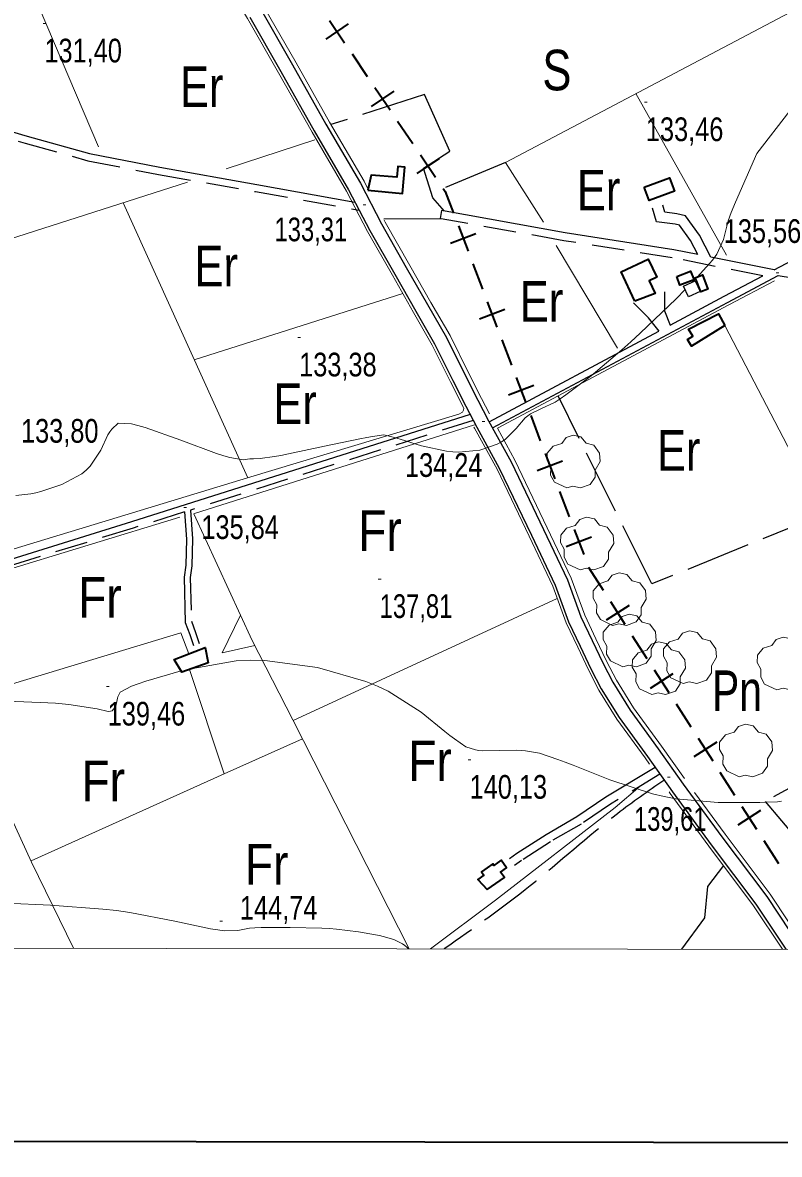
# Model space of a CAD drawing. Extents: x 487425 to 492029, y 4383576 to 4386788.
# Drawn here: x 488050.9 to 488330.4, y 4384052.3 to 4384470.4 of the extents above; entities that cross this region are included whole.
import ezdxf
from ezdxf.enums import TextEntityAlignment as Align

# ---------------------------------------------------------------- set-up
doc = ezdxf.new("R2010")
doc.units = 0
doc.header["$LTSCALE"] = 4
doc.linetypes.add('LONG_DASHED', pattern=[7.5, 6, -1.5])
doc.linetypes.add('MEDIUM_DASHED', pattern=[4.5, 3, -1.5])
for name, color, linetype, lineweight in [('1', 7, 'Continuous', 13), ('21', 7, 'Continuous', 25), ('25', 7, 'LONG_DASHED', 25), ('29', 7, 'Continuous', 13), ('34', 7, 'Continuous', 35), ('36', 7, 'Continuous', 25), ('38', 7, 'Continuous', 25), ('47', 7, 'Continuous', 35), ('51', 7, 'Continuous', 13), ('7', 7, 'Continuous', 13), ('9', 7, 'Continuous', 13)]:
    doc.layers.add(name, color=color, linetype=linetype, lineweight=lineweight)
doc.layers.add('31', color=7, linetype='Continuous')

msp = doc.modelspace()

# ---------------------------------------------------------------- linework, layer by layer
at = {"layer": '1', "lineweight": 35}
msp.add_lwpolyline([(487611.46, 4386512.7), (491328.86, 4386507.3), (491325.3, 4384052.3), (487607.9, 4384057.7)], close=True, dxfattribs=at)
at = {"layer": '1'}
msp.add_lwpolyline([(487681.9, 4386441.2), (491258.2, 4386436), (491255.4, 4384123.8), (487678, 4384129)], close=True, dxfattribs=at)
at = {"layer": '21'}
msp.add_lwpolyline([(488295.04, 4384373.01), (488299.32, 4384375.02), (488301.17, 4384371.07), (488296.89, 4384369.06)], close=True, dxfattribs=at)
at = {"layer": '25'}
for p, q in [((488229.24, 4384418.77), (488201.91, 4384407.26)), ((488205.48, 4384397.97), (488184.27, 4384397.75))]:
    msp.add_line(p, q, dxfattribs=at)
for points in [[(488206.75, 4384400.79), (488202.39, 4384405.72), (488198.91, 4384416.64), (488208.66, 4384422.91), (488199.29, 4384443.8), (488164.78, 4384432.73)], [(488346.6, 4384288.7), (488283.29, 4384263.01), (488248.67, 4384332.48)], [(488500.54, 4384232.57), (488391.47, 4384171.16), (488380.26, 4384174.51), (488371.03, 4384181.22), (488361.77, 4384197.9), (488349.22, 4384195.94), (488325.13, 4384182.64), (488337.28, 4384168.32), (488347.47, 4384167.38), (488352.97, 4384162.67), (488357.34, 4384157.74), (488366.14, 4384147.21), (488370.51, 4384135.61), (488372.62, 4384127.99)], [(488309.75, 4384159.04), (488303.85, 4384151.3), (488302.81, 4384139.68), (488294.31, 4384128.1)]]:
    msp.add_lwpolyline(points, dxfattribs=at)
at = {"layer": '29'}
for points in [[(488251.86, 4384298.56), (488247.32, 4384300.68), (488245.91, 4384303.22), (488246.01, 4384306.2), (488244.64, 4384308.61), (488244.68, 4384311.36), (488246.84, 4384313.96), (488250.03, 4384314.96), (488251.68, 4384317.15), (488254.25, 4384317.98), (488257.11, 4384317.33), (488259.06, 4384315.06), (488261.87, 4384314.24), (488264, 4384311.39), (488264.24, 4384308.26), (488262.36, 4384305.11), (488262.36, 4384302.43), (488260.54, 4384299.82), (488256.92, 4384298.48), (488254.15, 4384299.11)], [(488256.84, 4384268.27), (488252.3, 4384270.39), (488250.89, 4384272.93), (488250.99, 4384275.91), (488249.62, 4384278.32), (488249.66, 4384281.07), (488251.82, 4384283.67), (488255.01, 4384284.67), (488256.66, 4384286.86), (488259.23, 4384287.69), (488262.09, 4384287.04), (488264.04, 4384284.77), (488266.85, 4384283.95), (488268.98, 4384281.1), (488269.22, 4384277.97), (488267.34, 4384274.82), (488267.34, 4384272.14), (488265.52, 4384269.53), (488261.9, 4384268.19), (488259.13, 4384268.82)], [(488268.84, 4384247.73), (488264.3, 4384249.85), (488262.89, 4384252.39), (488262.99, 4384255.37), (488261.62, 4384257.78), (488261.66, 4384260.53), (488263.82, 4384263.13), (488267.01, 4384264.13), (488268.66, 4384266.32), (488271.23, 4384267.15), (488274.09, 4384266.5), (488276.04, 4384264.23), (488278.85, 4384263.41), (488280.98, 4384260.56), (488281.22, 4384257.43), (488279.34, 4384254.28), (488279.34, 4384251.6), (488277.52, 4384248.99), (488273.9, 4384247.65), (488271.13, 4384248.28)], [(488272.56, 4384232.46), (488268.02, 4384234.58), (488266.61, 4384237.12), (488266.71, 4384240.1), (488265.34, 4384242.51), (488265.38, 4384245.26), (488267.54, 4384247.86), (488270.73, 4384248.86), (488272.38, 4384251.05), (488274.95, 4384251.88), (488277.81, 4384251.23), (488279.76, 4384248.96), (488282.57, 4384248.14), (488284.7, 4384245.29), (488284.94, 4384242.16), (488283.06, 4384239.01), (488283.06, 4384236.33), (488281.24, 4384233.72), (488277.62, 4384232.38), (488274.85, 4384233.01)], [(488294.85, 4384226.28), (488290.31, 4384228.4), (488288.9, 4384230.94), (488289, 4384233.92), (488287.63, 4384236.33), (488287.67, 4384239.08), (488289.83, 4384241.68), (488293.02, 4384242.68), (488294.67, 4384244.87), (488297.24, 4384245.7), (488300.1, 4384245.05), (488302.05, 4384242.78), (488304.86, 4384241.96), (488306.99, 4384239.11), (488307.23, 4384235.98), (488305.35, 4384232.83), (488305.35, 4384230.15), (488303.53, 4384227.54), (488299.91, 4384226.2), (488297.14, 4384226.83)], [(488329.48, 4384223.93), (488324.94, 4384226.05), (488323.53, 4384228.59), (488323.63, 4384231.57), (488322.26, 4384233.98), (488322.3, 4384236.73), (488324.46, 4384239.33), (488327.65, 4384240.33), (488329.3, 4384242.52), (488331.87, 4384243.35), (488334.73, 4384242.7), (488336.68, 4384240.43), (488339.49, 4384239.61), (488341.62, 4384236.76), (488341.86, 4384233.63), (488339.98, 4384230.48), (488339.98, 4384227.8), (488338.16, 4384225.19), (488334.54, 4384223.85), (488331.77, 4384224.48)], [(488283.33, 4384222.21), (488278.79, 4384224.33), (488277.38, 4384226.87), (488277.48, 4384229.85), (488276.11, 4384232.26), (488276.15, 4384235.01), (488278.31, 4384237.61), (488281.5, 4384238.61), (488283.15, 4384240.8), (488285.72, 4384241.63), (488288.58, 4384240.98), (488290.53, 4384238.71), (488293.34, 4384237.89), (488295.47, 4384235.04), (488295.71, 4384231.91), (488293.83, 4384228.76), (488293.83, 4384226.08), (488292.01, 4384223.47), (488288.39, 4384222.13), (488285.62, 4384222.76)], [(488315.54, 4384191.83), (488311, 4384193.95), (488309.59, 4384196.49), (488309.69, 4384199.47), (488308.32, 4384201.88), (488308.36, 4384204.63), (488310.52, 4384207.23), (488313.71, 4384208.23), (488315.36, 4384210.42), (488317.93, 4384211.25), (488320.79, 4384210.6), (488322.74, 4384208.33), (488325.55, 4384207.51), (488327.68, 4384204.66), (488327.92, 4384201.53), (488326.04, 4384198.38), (488326.04, 4384195.7), (488324.22, 4384193.09), (488320.6, 4384191.75), (488317.83, 4384192.38)]]:
    msp.add_lwpolyline(points, close=True, dxfattribs=at)
at = {"layer": '34'}
for p, q in [((488171.14, 4384469.9), (488162.86, 4384464.29)), ((488164.19, 4384471.24), (488169.8, 4384462.95)), ((488172.6, 4384458.81), (488178.21, 4384450.53)), ((488187.95, 4384445.06), (488179.67, 4384439.46)), ((488181.01, 4384446.4), (488186.61, 4384438.12)), ((488189.41, 4384433.98), (488195.02, 4384425.7)), ((488197.82, 4384421.57), (488203.42, 4384413.28)), ((488204.76, 4384420.23), (488196.48, 4384414.62)), ((488218.3, 4384392.39), (488208.96, 4384388.83)), ((488211.85, 4384395.28), (488215.41, 4384385.94)), ((488217.19, 4384381.27), (488220.76, 4384371.92)), ((488222.53, 4384367.26), (488226.1, 4384357.92)), ((488228.99, 4384364.37), (488219.64, 4384360.81)), ((488227.88, 4384353.25), (488231.44, 4384343.9)), ((488233.22, 4384339.24), (488236.78, 4384329.9)), ((488239.67, 4384336.35), (488230.33, 4384332.79)), ((488238.56, 4384325.22), (488242.12, 4384315.88)), ((488243.9, 4384311.22), (488247.47, 4384301.87)), ((488250.36, 4384308.33), (488241.01, 4384304.76)), ((488249.25, 4384297.2), (488252.81, 4384287.86)), ((488261.04, 4384280.31), (488251.7, 4384276.74)), ((488254.59, 4384283.2), (488258.15, 4384273.85)), ((488274.9, 4384255.04), (488266.48, 4384249.64)), ((488267.99, 4384256.55), (488273.39, 4384248.13)), ((488276.09, 4384243.92), (488281.5, 4384235.51)), ((488291.1, 4384229.8), (488282.68, 4384224.4)), ((488284.19, 4384231.31), (488289.59, 4384222.89)), ((488292.29, 4384218.68), (488297.69, 4384210.27)), ((488307.3, 4384204.56), (488298.88, 4384199.16)), ((488300.39, 4384206.07), (488305.79, 4384197.65)), ((488308.49, 4384193.44), (488313.89, 4384185.03)), ((488323.5, 4384179.32), (488315.08, 4384173.92)), ((488316.59, 4384180.83), (488321.99, 4384172.41)), ((488324.69, 4384168.21), (488330.09, 4384159.79))]:
    msp.add_line(p, q, dxfattribs=at)
for points in [[(488206.23, 4384409.14), (488207, 4384408), (488210.07, 4384399.95)], [(488259.93, 4384269.18), (488260, 4384269), (488265.3, 4384260.75)]]:
    msp.add_lwpolyline(points, dxfattribs=at)
at = {"layer": '36'}
for points in [[(488134.8, 4384472.39), (488146.25, 4384452.35), (488158.62, 4384430.43), (488171.32, 4384408.65), (488179.09, 4384393.64), (488188.32, 4384377.51), (488196.12, 4384363.84), (488203.07, 4384351.75), (488209.85, 4384338.18), (488214.63, 4384328.65), (488218.61, 4384320.97), (488226.97, 4384305.84), (488238.81, 4384281.03), (488247.6, 4384262.62), (488252.55, 4384248.99), (488256.79, 4384240.03), (488260.77, 4384231.68), (488264.59, 4384224.27), (488271.21, 4384213.65), (488281.67, 4384199.28), (488290.9, 4384186.19), (488305.19, 4384166.71), (488321.7, 4384144.67), (488332.78, 4384128.05)], [(488139.09, 4384474.89), (488150.57, 4384454.8), (488162.92, 4384432.9), (488175.67, 4384411.04), (488183.45, 4384396.02), (488192.62, 4384379.97), (488200.42, 4384366.3), (488207.44, 4384354.1), (488214.28, 4384340.4), (488219.04, 4384330.9), (488222.99, 4384323.32), (488231.38, 4384308.11), (488243.29, 4384283.17), (488252.18, 4384264.54), (488257.14, 4384250.9), (488261.27, 4384242.16), (488265.21, 4384233.89), (488268.91, 4384226.73), (488275.32, 4384216.42), (488285.7, 4384202.17), (488294.93, 4384189.09), (488309.18, 4384169.66), (488325.75, 4384147.54), (488338.74, 4384128.04)]]:
    msp.add_lwpolyline(points, dxfattribs=at)
at = {"layer": '38'}
for p, q in [((488205.67, 4384400.98), (488205.14, 4384398.03)), ((488328.53, 4384379.07), (488305.12, 4384383.73)), ((488223.18, 4384322.97), (488285.96, 4384356.44))]:
    msp.add_line(p, q, dxfattribs=at)
at = {"layer": '38', "linetype": 'MEDIUM_DASHED'}
msp.add_line((488217.35, 4384323.41), (488112.87, 4384290.33), dxfattribs=at)
for points in [[(487779.74, 4384690.68), (487796.4, 4384662.21), (487807.82, 4384640.76), (487818.34, 4384620.97), (487828.28, 4384603.12), (487836.46, 4384588.37), (487848.09, 4384573.5), (487857.95, 4384559.67), (487871.77, 4384543.86), (487886.51, 4384528.08), (487900.7, 4384514.1), (487914.75, 4384501.89), (487934.42, 4384487.46), (487949.34, 4384475.26), (487970.33, 4384463.51), (487994.05, 4384450.1), (488013.2, 4384439.84), (488031.96, 4384431.72), (488051.87, 4384425.89), (488075.02, 4384419.37), (488101.05, 4384414.32), (488136.94, 4384407.99), (488175.23, 4384401.1)], [(488300.28, 4384384.7), (488297.61, 4384389.86), (488293.52, 4384395.55), (488291.91, 4384395.92), (488285.1, 4384396.82), (488283.62, 4384401.88)], [(488324.35, 4384376.84), (488290.85, 4384383.52), (488250.8, 4384389.82), (488205.48, 4384397.97)], [(488329.99, 4384376.93), (488354.6, 4384373.09), (488370.18, 4384370.59), (488382.08, 4384368.65), (488393.06, 4384366.95), (488406.14, 4384363.89), (488419.04, 4384361.34), (488433.17, 4384356.71), (488453.19, 4384349.88), (488470.41, 4384343.54), (488497.54, 4384332.84)], [(488110.65, 4384289.63), (488091.76, 4384283.65), (488007.45, 4384257.85)], [(488112.87, 4384290.33), (488113.65, 4384279.69), (488113.38, 4384269.75), (488112.81, 4384265.36), (488113.22, 4384249.28), (488114.76, 4384245.14), (488116.15, 4384241.06)], [(488286.28, 4384192.74), (488268, 4384181.66), (488257.18, 4384174.34), (488245.83, 4384167.79), (488235.18, 4384160.91), (488232.57, 4384159.02)]]:
    msp.add_lwpolyline(points, dxfattribs=at)
at = {"layer": '38'}
for points in [[(487781.71, 4384691.75), (487798.75, 4384663.55), (487810.21, 4384642.03), (487820.71, 4384622.26), (487830.64, 4384604.44), (487838.72, 4384589.87), (487850.26, 4384575.11), (487860.07, 4384561.35), (487873.77, 4384545.67), (487888.45, 4384529.97), (487902.54, 4384516.08), (487916.44, 4384504), (487936.07, 4384489.6), (487950.86, 4384477.51), (487971.66, 4384465.87), (487995.36, 4384452.47), (488014.37, 4384442.27), (488032.88, 4384434.26), (488052.62, 4384428.48), (488075.64, 4384422.01), (488101.54, 4384416.98), (488137.41, 4384410.65), (488173.66, 4384404.13)], [(488328.53, 4384379.07), (488378.84, 4384405.72), (488554.77, 4384499.82), (488556.14, 4384500.56)], [(488300.28, 4384384.7), (488291.38, 4384386.47), (488251.3, 4384392.78), (488205.67, 4384400.98)], [(488305.12, 4384383.73), (488300.91, 4384391.88), (488295.81, 4384398.98), (488292.6, 4384399.72), (488288.1, 4384400.32), (488287.32, 4384402.97)], [(488224.43, 4384320.72), (488311.29, 4384367.02), (488329.99, 4384376.93)], [(488290.1, 4384358.64), (488310.08, 4384369.29), (488324.35, 4384376.84)], [(488287.97, 4384370.99), (488288.04, 4384363.94), (488290.08, 4384358.66)], [(488285.97, 4384356.44), (488282.08, 4384361.38), (488276.59, 4384366.84)], [(488216.23, 4384325.57), (488091.04, 4384285.94), (488009.73, 4384260.6)], [(488110.65, 4384289.63), (488111.38, 4384279.63), (488111.12, 4384269.93), (488110.54, 4384265.48), (488110.97, 4384248.84), (488112.63, 4384244.39), (488114, 4384240.33)], [(488284.51, 4384195.25), (488266.35, 4384184.23), (488255.55, 4384176.94), (488244.23, 4384170.4), (488233.45, 4384163.43), (488230.77, 4384161.49)]]:
    msp.add_lwpolyline(points, dxfattribs=at)
at = {"layer": '38', "linetype": 'LONG_DASHED'}
msp.add_spline([(488287.71, 4384190.42), (488270.62, 4384178.16), (488238.43, 4384151.52), (488206.62, 4384128.23)], degree=3, dxfattribs=at)
at = {"layer": '47'}
for points in [[(488178.41, 4384408.47), (488191.15, 4384407.28), (488192.06, 4384417.06), (488189.43, 4384417.29), (488189.07, 4384413.25), (488179.64, 4384414.01)], [(488280.53, 4384409.64), (488289.87, 4384413.06), (488291.69, 4384408.08), (488282.35, 4384404.66)], [(488277.05, 4384367.51), (488272, 4384378.37), (488282.02, 4384383.04), (488285.14, 4384376.32), (488282.38, 4384375.05), (488284.57, 4384370.27)], [(488292.61, 4384376.56), (488297.65, 4384378.53), (488298.67, 4384375.89), (488302.01, 4384377.19), (488304.04, 4384371.96), (488301.42, 4384370.95), (488299.6, 4384375.64), (488293.65, 4384373.35)], [(488310.26, 4384358.51), (488297.94, 4384350.92), (488296.44, 4384353.33), (488298.45, 4384354.58), (488296.84, 4384357.15), (488307.9, 4384362.81)], [(488119.48, 4384233.89), (488109.69, 4384230.4), (488106.89, 4384235.16), (488118.27, 4384239.61)], [(488222.51, 4384150.12), (488228.86, 4384154.62), (488227.45, 4384156.6), (488229.68, 4384158.2), (488227.68, 4384160.98), (488224.98, 4384159.04), (488224.56, 4384159.62), (488220.41, 4384156.62), (488221.29, 4384155.4), (488219.05, 4384153.79)]]:
    msp.add_lwpolyline(points, close=True, dxfattribs=at)
at = {"layer": '51'}
for p, q in [((488056.97, 4384476.02), (488078.96, 4384424.53)), ((488277.35, 4384444.17), (488310.93, 4384384.53)), ((488158.82, 4384427.08), (488126.06, 4384416.42)), ((488087.99, 4384403.83), (488134.02, 4384302.25)), ((488247.95, 4384388.03), (488270.62, 4384350.18)), ((488114.29, 4384345.81), (488191.31, 4384370.35)), ((488310.26, 4384358.51), (488346.6, 4384288.7)), ((488150.8, 4384212.62), (488248.39, 4384257.67)), ((488125.32, 4384192.86), (488053.98, 4384160.7))]:
    msp.add_line(p, q, dxfattribs=at)
for points in [[(488085.4, 4384586.45), (488087.77, 4384578.37), (488092.03, 4384568.22), (488096.62, 4384558.1), (488101.98, 4384546.59), (488106.93, 4384534.96), (488111.26, 4384526.34), (488118.56, 4384512.85), (488129.85, 4384493.35), (488140.39, 4384475.65), (488151.88, 4384455.55), (488164.23, 4384433.65), (488176.99, 4384411.77), (488178.55, 4384408.77)], [(488114.88, 4384504.4), (488123.46, 4384489.59), (488133.98, 4384471.91), (488145.42, 4384451.88), (488157.79, 4384429.96), (488170.49, 4384408.19), (488178.25, 4384393.18), (488187.49, 4384377.04), (488195.29, 4384363.37), (488202.23, 4384351.3), (488209, 4384337.75), (488213.78, 4384328.22), (488213.9, 4384328.01)], [(488243.25, 4384396.71), (488229.24, 4384418.77), (488361.1, 4384488.39), (488398.73, 4384417.9)], [(488111.75, 4384411.41), (487960.93, 4384363.23), (487917.97, 4384470.37)], [(488223.36, 4384325.9), (488220.39, 4384331.59), (488215.63, 4384341.08), (488208.77, 4384354.81), (488201.73, 4384367.05), (488193.93, 4384380.72), (488184.78, 4384396.74), (488184.45, 4384397.39)], [(488226.26, 4384320.53), (488311.77, 4384366.11), (488328.66, 4384375.06)], [(487962.83, 4384363.84), (488000.6, 4384262.63), (488002.32, 4384262.16), (488133.91, 4384302.22), (488211.98, 4384325.72), (488213.34, 4384326.53), (488213.49, 4384326.75), (488213.72, 4384327.2), (488213.9, 4384328.01)], [(488193.68, 4384128.25), (488150.68, 4384212.83), (488135.71, 4384242.11), (488114.18, 4384288.87), (488114.33, 4384289.02), (488217.86, 4384321.75)], [(488217.54, 4384320.99), (488217.77, 4384320.52), (488226.12, 4384305.4), (488237.95, 4384280.62), (488246.72, 4384262.25), (488251.67, 4384248.62), (488255.93, 4384239.62), (488259.92, 4384231.26), (488263.76, 4384223.8), (488270.42, 4384213.12), (488280.9, 4384198.73), (488282.48, 4384196.5)], [(488226.26, 4384320.53), (488232.72, 4384308.8), (488244.65, 4384283.82), (488253.57, 4384265.12), (488258.54, 4384251.48), (488262.63, 4384242.81), (488266.56, 4384234.56), (488270.22, 4384227.48), (488276.57, 4384217.26), (488286.93, 4384203.05), (488295.36, 4384191.11)], [(488108.99, 4384287.65), (488007.21, 4384256.63), (488026.45, 4384220.55), (488054.2, 4384160.21), (488069.69, 4384128.43)], [(488136.67, 4384240.25), (488124.55, 4384237.59), (488131.39, 4384251.52)], [(488026.71, 4384220), (488109.33, 4384244.96), (488112.22, 4384237.25)], [(488112.51, 4384231.41), (488125.32, 4384192.86), (488154.26, 4384205.81)], [(488201.55, 4384128.24), (488225.62, 4384146.18), (488269.74, 4384180.42), (488279.06, 4384188.34)], [(488289.73, 4384186.21), (488290.13, 4384185.63), (488304.43, 4384166.14), (488320.92, 4384144.12), (488331.63, 4384128.05)], [(488299.08, 4384186), (488310.39, 4384170.56), (488326.98, 4384148.41), (488340.56, 4384128.04)]]:
    msp.add_lwpolyline(points, dxfattribs=at)
at = {"layer": '7'}
for p, q in [((488058.43, 4384470.07), (488059.43, 4384470.07)), ((488280.61, 4384440.99), (488281.61, 4384440.99)), ((488176.72, 4384403.08), (488177.72, 4384403.08)), ((488329.26, 4384377.94), (488330.26, 4384377.94)), ((488152.53, 4384354.07), (488153.53, 4384354.07)), ((488220.68, 4384323.06), (488221.68, 4384323.06)), ((488110.41, 4384291.23), (488111.41, 4384291.23)), ((488182.28, 4384264.83), (488183.28, 4384264.83)), ((488081.82, 4384225.09), (488082.82, 4384225.09)), ((488215.5, 4384198.06), (488216.5, 4384198.06)), ((488289.1, 4384191.67), (488290.1, 4384191.67)), ((488123.75, 4384138.41), (488124.75, 4384138.41))]:
    msp.add_line(p, q, dxfattribs=at)
at = {"layer": '9'}
for p, q in [((488298.17, 4384374.48), (488299.09, 4384375.44)), ((488096.41, 4384227.08), (488109.41, 4384230.87))]:
    msp.add_line(p, q, dxfattribs=at)
for points in [[(488300.01, 4384376.41), (488303.57, 4384380.14), (488305.67, 4384382.66), (488307.35, 4384384.87), (488309.81, 4384390.24), (488311.49, 4384397.14), (488312.67, 4384400.31), (488314.16, 4384404.04), (488322.12, 4384422.07), (488334.25, 4384437.79)], [(488048.36, 4384295.72), (488053.94, 4384296.33), (488055.74, 4384296.72), (488057.64, 4384297.22), (488065.4, 4384299.82), (488072.74, 4384303.75), (488074.38, 4384305.07), (488075.85, 4384306.49), (488079.73, 4384312.49), (488082.41, 4384318.07), (488083.11, 4384319.24), (488083.81, 4384320.23), (488086.18, 4384322.44), (488091.11, 4384322.15), (488093.41, 4384321.57), (488096.12, 4384320.77), (488109.27, 4384316.09), (488122.44, 4384311.27), (488125.15, 4384310.39), (488127.45, 4384309.7), (488132.41, 4384308.85), (488134.78, 4384309.19), (488135.46, 4384309.26), (488136.14, 4384309.31), (488138.69, 4384309.41), (488143.91, 4384310.1), (488146.27, 4384310.54), (488149.04, 4384311.07), (488162.35, 4384313.88), (488175.4, 4384316.65), (488178.01, 4384317.16), (488180.18, 4384317.56), (488184.35, 4384318.1), (488187.28, 4384317.37), (488188.67, 4384316.98), (488190.3, 4384316.51), (488198.28, 4384314.11), (488207.41, 4384312.07), (488209.78, 4384311.83), (488212.07, 4384311.71), (488219.77, 4384312.45), (488226.22, 4384314.67), (488227.73, 4384315.49), (488229.12, 4384316.4), (488233.14, 4384320.43), (488236.52, 4384324.35), (488237.5, 4384325.19), (488238.51, 4384325.92), (488242.31, 4384327.69), (488247.56, 4384330.21), (488249.48, 4384331.43), (488251.59, 4384332.87), (488260.9, 4384339.93), (488272.19, 4384349.48), (488275.55, 4384352.48), (488279.01, 4384355.65), (488292.36, 4384368.4), (488295.61, 4384371.8)], [(488113.71, 4384231.83), (488129.78, 4384234.59), (488135.02, 4384234.82), (488140.3, 4384234.76), (488159.75, 4384232.19), (488177.64, 4384226.98), (488181.94, 4384225.25), (488185.95, 4384223.4), (488198.05, 4384215.69), (488206.83, 4384208.54), (488208.74, 4384207.05), (488210.42, 4384205.76), (488214.62, 4384202.86), (488218.17, 4384201.72), (488219.45, 4384201.54), (488220.85, 4384201.42), (488226.97, 4384201.48), (488233.47, 4384201.59), (488235.11, 4384201.51), (488236.69, 4384201.37), (488241.79, 4384200.46), (488248.62, 4384198.19), (488251.28, 4384197.2), (488254.27, 4384196.06), (488267.84, 4384190.63), (488283.56, 4384185.44), (488287.9, 4384184.45), (488292.23, 4384183.64), (488307.85, 4384182.35), (488320.69, 4384182.34), (488323.27, 4384182.35), (488325.44, 4384182.37), (488329.77, 4384182.48), (488331.22, 4384182.77)], [(488029.94, 4384220.33), (488057.39, 4384219.29), (488063.07, 4384218.93), (488067.9, 4384218.55), (488078.38, 4384216.92), (488082.5, 4384215.96), (488083.32, 4384215.99), (488083.99, 4384216.16), (488085.29, 4384217.88), (488085.76, 4384220.24), (488085.92, 4384220.82), (488086.1, 4384221.37), (488086.86, 4384223.08), (488091.12, 4384225.27), (488093.51, 4384226.12), (488096.41, 4384227.08)], [(488044.83, 4384145.06), (488061.2, 4384144.41), (488080.54, 4384142.93), (488085.59, 4384142.33), (488090.5, 4384141.65), (488107.14, 4384138.47), (488120.29, 4384135.67), (488123, 4384135.22), (488125.32, 4384134.92), (488130.32, 4384135.01), (488134.74, 4384135.81), (488136.69, 4384135.95), (488138.95, 4384136.06), (488149.72, 4384136.16), (488161.38, 4384135.84), (488164.21, 4384135.68), (488166.86, 4384135.49), (488174.98, 4384134.56), (488181.23, 4384133.44), (488182.7, 4384133.14), (488184.06, 4384132.83), (488188.05, 4384131.72), (488191.22, 4384130.06), (488192.06, 4384129.41), (488192.89, 4384128.68), (488193.26, 4384128.25)]]:
    msp.add_lwpolyline(points, dxfattribs=at)

# ---------------------------------------------------------------- texts
at = {"layer": '31'}
for s, width, p in [('S', 0.8, (488248.24, 4384445.38)), ('Er', 0.8, (488117.02, 4384439.22)), ('Er', 0.8, (488263.66, 4384401)), ('Er', 0.8, (488122.41, 4384372.95)), ('Er', 0.8, (488242.57, 4384359.91)), ('Er', 0.8, (488151.53, 4384322.1)), ('Er', 0.8, (488293.24, 4384304.84)), ('Fr', 0.85, (488182.93, 4384275.25)), ('Fr', 0.85, (488079.42, 4384250.59)), ('Pn', 0.75, (488314.78, 4384216.07)), ('Fr', 0.85, (488201.41, 4384190.18)), ('Fr', 0.85, (488080.65, 4384182.78)), ('Fr', 0.85, (488141.03, 4384151.96))]:
    msp.add_text(s, height=15, dxfattribs=dict(at, width=width)).set_placement(p, align=Align.CENTER)
at = {"layer": '7'}
for s, width, p in [('131,40', 0.8, (488058.93, 4384455.7)), ('133,46', 0.8, (488281.11, 4384426.62)), ('133,31', 0.75, (488143.94, 4384389.63)), ('135,56', 0.8, (488309.88, 4384389.01)), ('133,38', 0.8, (488153.03, 4384339.7)), ('133,80', 0.8, (488050.28, 4384315.21)), ('134,24', 0.8, (488192.11, 4384302.58)), ('135,84', 0.8, (488116.92, 4384279.64)), ('137,81', 0.75, (488182.78, 4384250.46)), ('139,46', 0.8, (488082.32, 4384210.72)), ('140,13', 0.8, (488216, 4384183.69)), ('139,61', 0.75, (488276.71, 4384171.82)), ('144,74', 0.8, (488131.14, 4384138.98))]:
    msp.add_text(s, height=8.75, dxfattribs=dict(at, width=width)).set_placement(p)

doc.saveas('drawing.dxf')
